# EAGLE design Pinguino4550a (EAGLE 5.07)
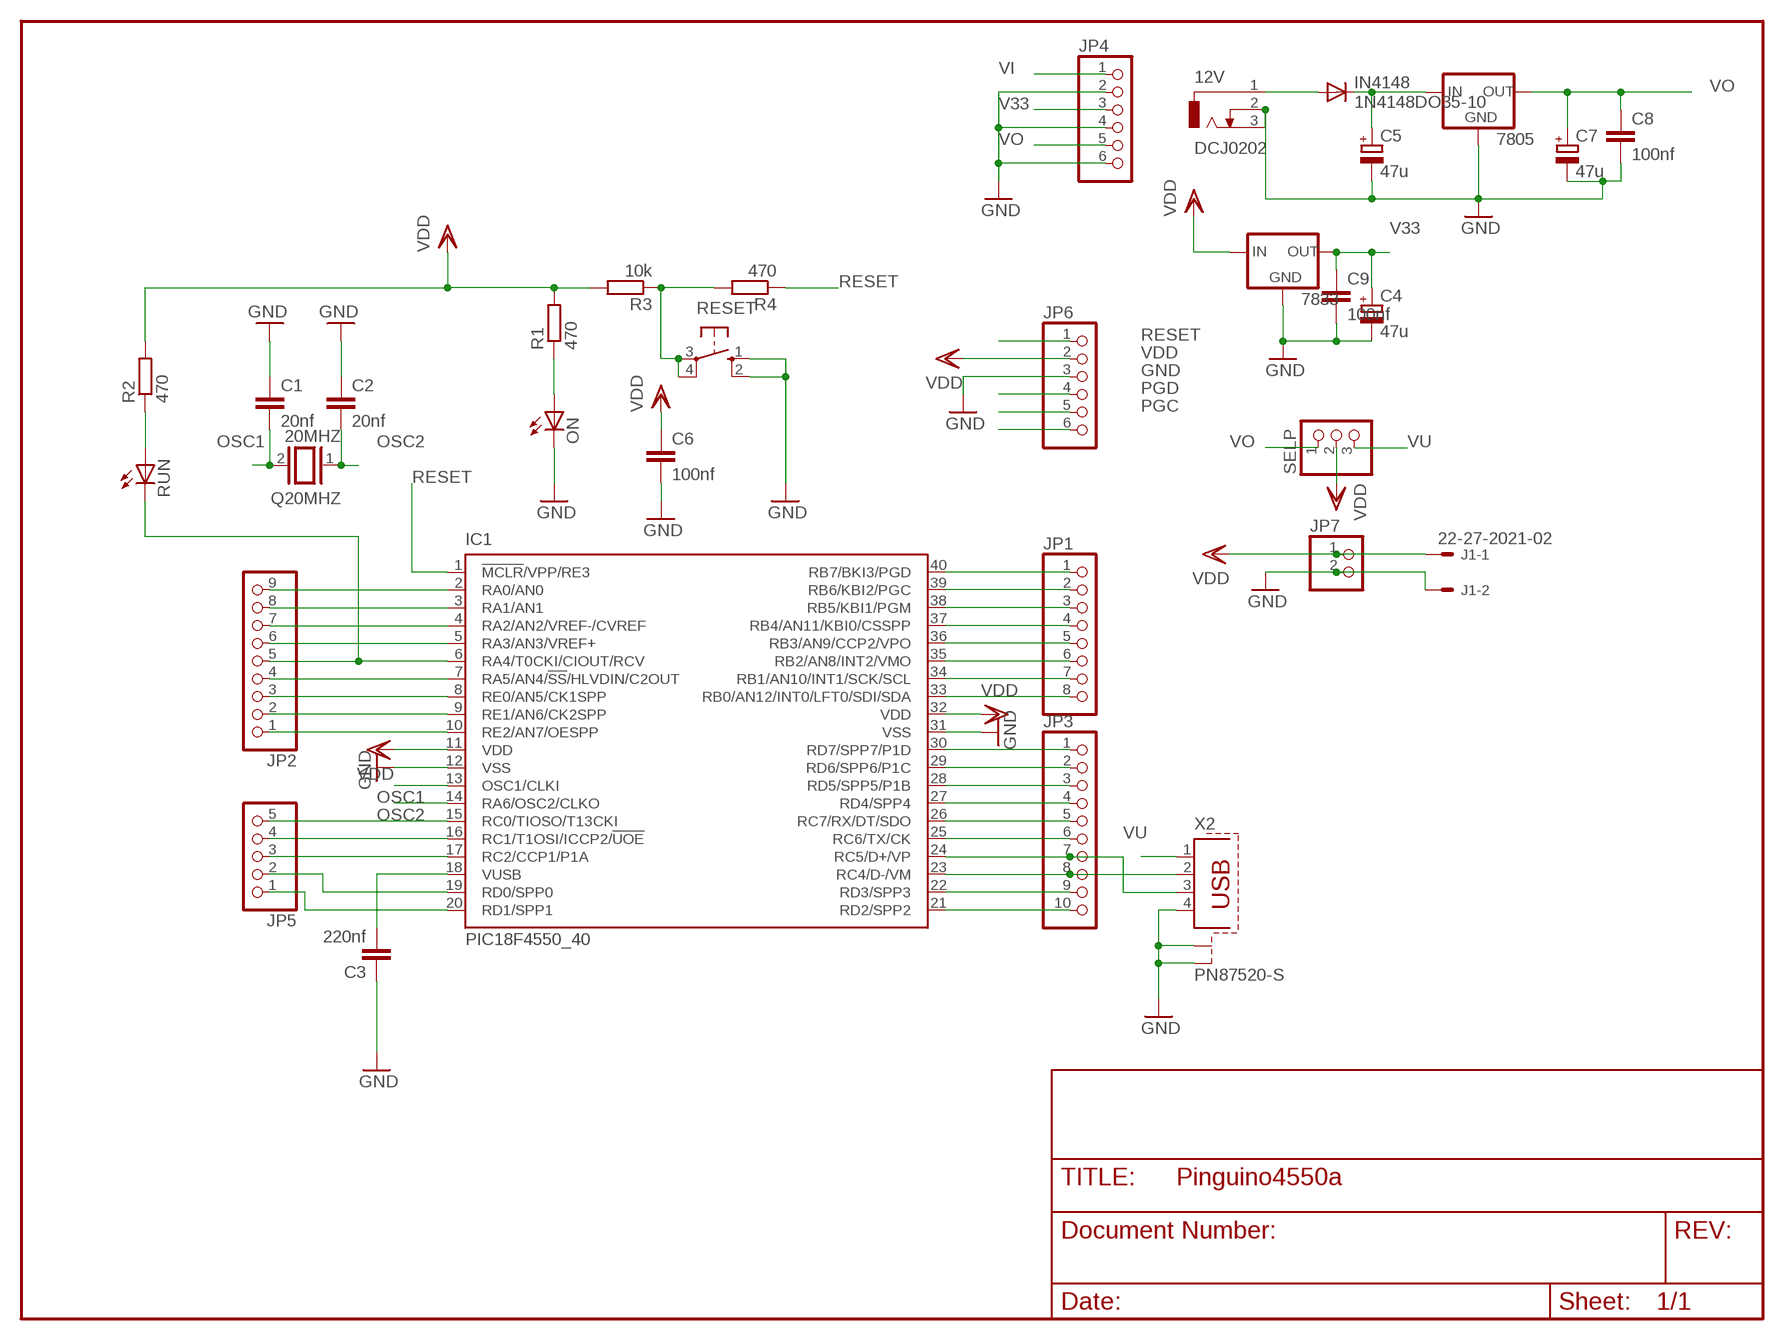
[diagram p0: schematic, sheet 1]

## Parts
12V  DCJ0202  [DCJ0202]
7805  78XXS  [78XXS]
7833  78XXS  [78XXS]
C1  20nf  C-EU025-024X044  [C025-024X044]
C2  20nf  C-EU025-024X044  [C025-024X044]
C3  220nf  C-EU025-024X044  [C025-024X044]
C4  47u  CPOL-EUE5-5  [E5-5]
C5  47u  CPOL-EUE5-5  [E5-5]
C6  100nf  C-EU025-024X044  [C025-024X044]
C7  47u  CPOL-EUE5-5  [E5-5]
C8  100nf  C-EU025-024X044  [C025-024X044]
C9  100nf  C-EU025-024X044  [C025-024X044]
IC1  PIC18F4550_40  [DIL40]
IN4148  1N4148DO35-10  [DO35-10]
J1  22-27-2021-02  [6410-02]
JP1  PINHD-1X8  [1X08]
JP2  PINHD-1X9  [1X09]
JP3  PINHD-1X10  [1X10]
JP4  PINHD-1X6  [1X06]
JP5  PINHD-1X5  [1X05]
JP6  PINHD-1X6  [1X06]
JP7  PINHD-1X2  [1X02]
ON  LED3MM  [LED3MM]
Q20MHZ  20MHZ  XTAL/S  [QS]
R1  470  R-EU_0204/7  [0204/7]
R2  470  R-EU_0204/7  [0204/7]
R3  10k  R-EU_0204/7  [0204/7]
R4  470  R-EU_0204/7  [0204/7]
RESET  10-XX  [B3F-10XX]
RUN  LED3MM  [LED3MM]
SELP  PINHD-1X3  [1X03]
X2  PN87520-S  [PN87520-S]

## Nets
GND: 12V.2 12V.3 7805.GND 7833.GND C1.1 C2.1 C3.1 C4.- C5.- C6.2 C7.- C8.2 C9.2 IC1.12(VSS) IC1.31(VSS) J1.2 JP4.2 JP4.4 JP4.6 JP6.3 JP7.2 ON.K(C) RESET.1(S) RESET.2(S1) X2.4 X2.S1 X2.S2
N$1: IC1.2(RA0/AN0) JP2.9
N$2: IC1.3(RA1/AN1) JP2.8
N$3: IC1.4(RA2/AN2/VREF-/CVREF) JP2.7
N$4: IC1.5(RA3/AN3/VREF+) JP2.6
N$5: R2.1 RUN.A
N$6: IC1.7(RA5/AN4/!SS!/HLVDIN/C2OUT) JP2.4
N$7: C3.2 IC1.18(VUSB)
N$8: IC1.8(RE0/AN5/CK1SPP) JP2.3
N$9: IC1.9(RE1/AN6/CK2SPP) JP2.2
N$10: IC1.30(RD7/SPP7/P1D) JP3.1
N$11: IC1.29(RD6/SPP6/P1C) JP3.2
N$12: IC1.33(RB0/AN12/INT0/LFT0/SDI/SDA) JP1.8
N$13: IC1.34(RB1/AN10/INT1/SCK/SCL) JP1.7
N$14: IC1.35(RB2/AN8/INT2/VMO) JP1.6
N$15: IC1.36(RB3/AN9/CCP2/VPO) JP1.5
N$16: IC1.37(RB4/AN11/KBI0/CSSPP) JP1.4
N$17: IC1.38(RB5/KBI1/PGM) JP1.3
N$18: R3.1 R4.2 RESET.3(P) RESET.4(P1)
N$19: IC1.10(RE2/AN7/OESPP) JP2.1
N$20: IC1.15(RC0/TIOSO/T13CKI) JP5.5
N$21: IC1.16(RC1/T1OSI/ICCP2/!UOE) JP5.4
N$22: IC1.17(RC2/CCP1/P1A) JP5.3
N$23: IC1.19(RD0/SPP0) JP5.2
N$24: 12V.1 IN4148.A
N$25: IC1.20(RD1/SPP1) JP5.1
N$26: JP6.6
N$27: IC1.28(RD5/SPP5/P1B) JP3.3
N$28: IC1.23(RC4/D-/VM) JP3.8 X2.2
N$29: IC1.24(RC5/D+/VP) JP3.7 X2.3
N$30: IC1.27(RD4/SPP4) JP3.4
N$31: IC1.26(RC7/RX/DT/SDO) JP3.5
N$32: IC1.25(RC6/TX/CK) JP3.6
N$33: IC1.22(RD3/SPP3) JP3.9
N$34: IC1.21(RD2/SPP2) JP3.10
N$41: IC1.6(RA4/T0CKI/CIOUT/RCV) JP2.5 RUN.K(C)
N$43: ON.A R1.1
OSC1: C1.2 IC1.13(OSC1/CLKI) Q20MHZ.2
OSC2: C2.2 IC1.14(RA6/OSC2/CLKO) Q20MHZ.1
PGC: IC1.39(RB6/KBI2/PGC) JP1.2 JP6.5
PGD: IC1.40(RB7/BKI3/PGD) JP1.1 JP6.4
RESET: IC1.1(!MCLR!/VPP/RE3) JP6.1 R4.1
V33: 7833.OUT C4.+ C9.1 JP4.3
VDD: 7833.IN C6.1 IC1.11(VDD) IC1.32(VDD) J1.1 JP6.2 JP7.1 R1.2 R2.2 R3.2 SELP.2
VI: 7805.IN C5.+ IN4148.C JP4.1
VO: 7805.OUT C7.+ C8.1 JP4.5 SELP.1
VU: SELP.3 X2.1

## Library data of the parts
12V = con-jack:DCJ0202: DC POWER JACK Source: DCJ0202.pdf
7805 7833 = v-reg:78XXS: VOLTAGE REGULATOR
C1-C3 C6 C8 C9 = rcl:C-EU: CAPACITOR, European symbol
C4 C5 C7 = rcl:CPOL-EU: POLARIZED CAPACITOR, European symbol
IC1 = microchip:PIC18F4*_40: USB Microcontrollers with nanoWatt Technology High-Performance, Enhanced Flash, 28/40/44-Pin, Source: http://ww1.microchip.com/downloads/en/devicedoc/39632c.pdf
IN4148 = diode:1N4148: DIODE
J1 = con-molex:22-?-02: CONNECTOR
JP1 = pinhead:PINHD-1X8: PIN HEADER
JP2 = pinhead:PINHD-1X9: PIN HEADER
JP3 = pinhead:PINHD-1X10: PIN HEADER
JP4 JP6 = pinhead:PINHD-1X6: PIN HEADER
JP5 = pinhead:PINHD-1X5: PIN HEADER
JP7 = pinhead:PINHD-1X2: PIN HEADER
ON RUN = led:LED: LED
Q20MHZ = special:XTAL/S: CRYSTAL
R1-R4 = rcl:R-EU_: RESISTOR, European symbol
RESET = switch-omron:10-XX: OMRON SWITCH
SELP = pinhead:PINHD-1X3: PIN HEADER
X2 = con-berg:PN87520-S

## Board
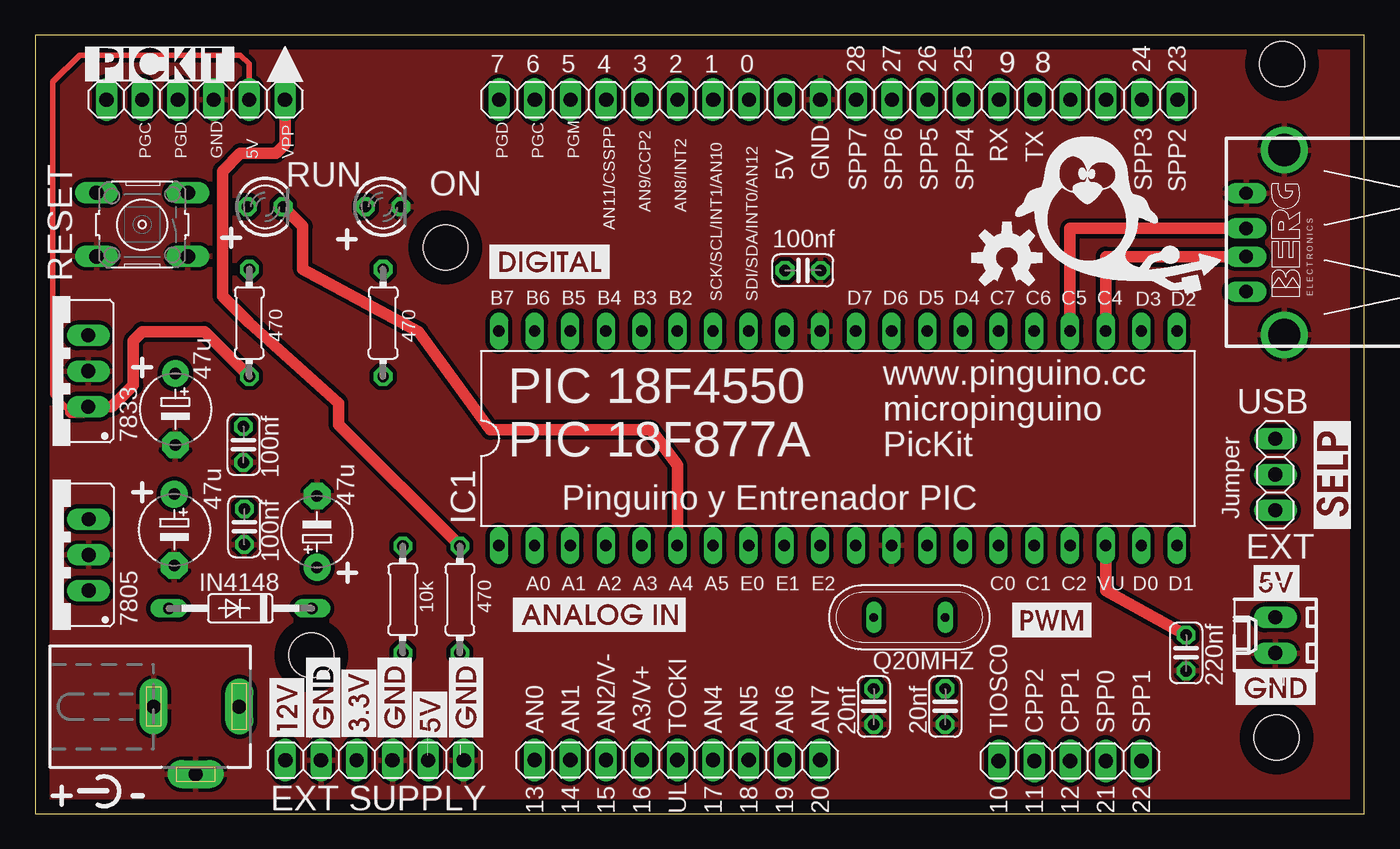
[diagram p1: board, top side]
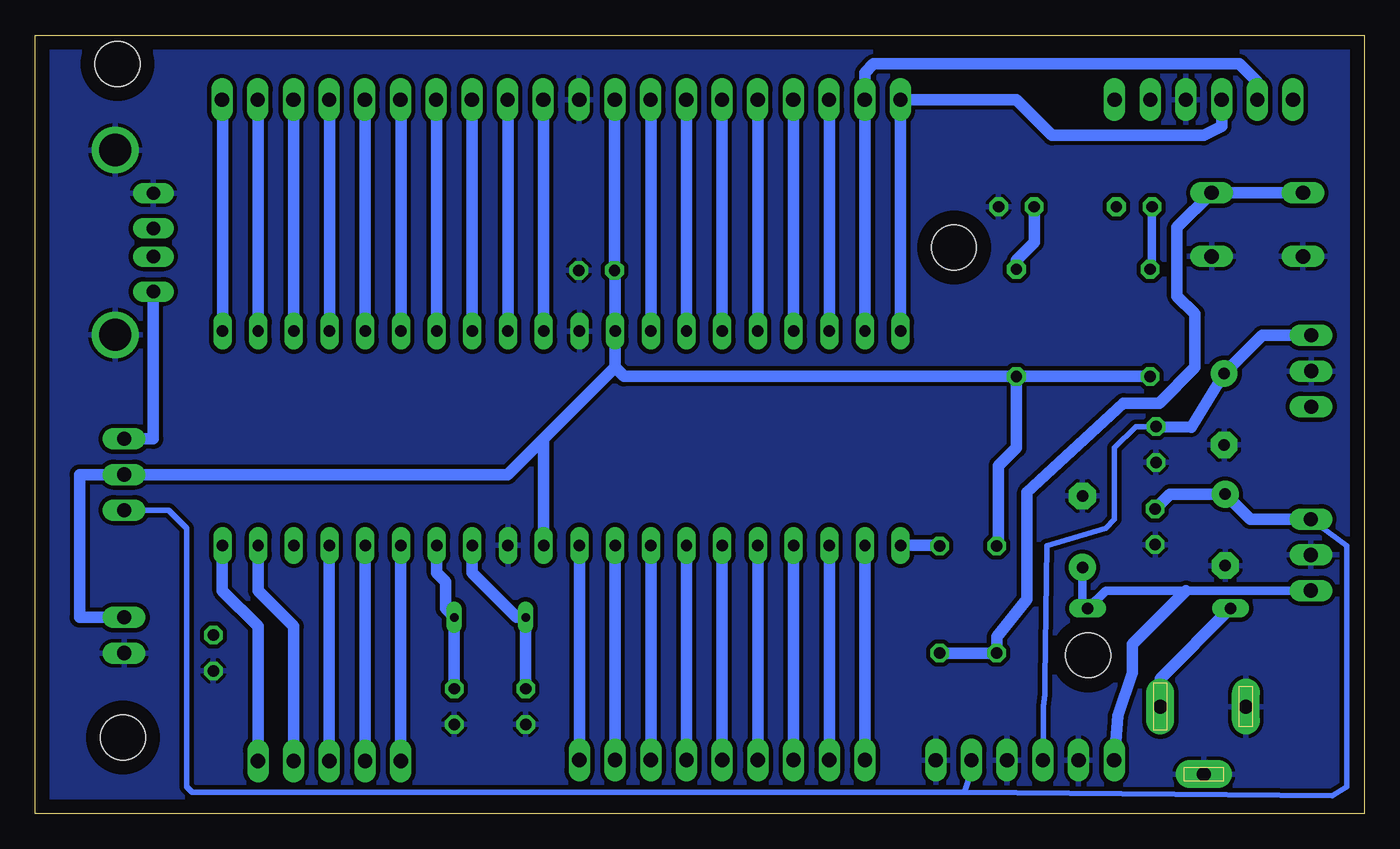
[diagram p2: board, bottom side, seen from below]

Size 94.6 x 55.39 mm. Coordinates in mm from the lower left corner, seen from the top.
Outline: 0,0 94.6,0 94.6,55.39 0,55.39 0,0
Copper layers (1*16): Top 0.035mm / dielectric 1.5mm / Bottom 0.035mm
Design rules "default": minimum track width 10mil, minimum drill 24mil, track to track 8mil, track to pad 8mil, pad to pad 8mil, via to via 8mil, smd to smd 8mil, copper to edge 40mil, drill to drill 8mil, minimum pad ring 10mil, minimum via ring 8mil, stop-mask expansion 4mil, vias tented up to drill 0mil, thermal gap 10mil
Holes 3.2 mm at 29.21,40.29 88.36,5.42 88.73,53.34 19.66,11.27

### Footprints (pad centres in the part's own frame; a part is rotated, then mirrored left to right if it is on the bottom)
DCJ0202 = drill 1 pad 2 long: 1 0,3.1; 2 4.8,0; 3 0,-3
78XXS = drill 1.016 long: GND 0,-2.54; IN -2.54,-2.54; OUT 2.54,-2.54
C025-024X044 = drill 0.813 octagon: 1 -1.27,0; 2 1.27,0
E5-5 = drill 0.813 pad 1.905 round: + -2.54,0 | drill 0.813 pad 1.905 octagon: - 2.54,0
DIL40 = drill 0.813 long: 1 -24.13,-7.62; 2 -21.59,-7.62; 3 -19.05,-7.62; 4 -16.51,-7.62; 5 -13.97,-7.62; 6 -11.43,-7.62; 7 -8.89,-7.62; 8 -6.35,-7.62; 9 -3.81,-7.62; 10 -1.27,-7.62; 11 1.27,-7.62; 12 3.81,-7.62; 13 6.35,-7.62; 14 8.89,-7.62; 15 11.43,-7.62; 16 13.97,-7.62; 17 16.51,-7.62; 18 19.05,-7.62; 19 21.59,-7.62; 20 24.13,-7.62; 21 24.13,7.62; 22 21.59,7.62; 23 19.05,7.62; 24 16.51,7.62; 25 13.97,7.62; 26 11.43,7.62; 27 8.89,7.62; 28 6.35,7.62; 29 3.81,7.62; 30 1.27,7.62; 31 -1.27,7.62; 32 -3.81,7.62; 33 -6.35,7.62; 34 -8.89,7.62; 35 -11.43,7.62; 36 -13.97,7.62; 37 -16.51,7.62; 38 -19.05,7.62; 39 -21.59,7.62; 40 -24.13,7.62
DO35-10 = drill 0.813 long: A 5.08,0; C -5.08,0
6410-02 = drill 1.016 long: 1 1.27,0; 2 -1.27,0
1X08 = drill 1.016 long: 1 -8.89,0; 2 -6.35,0; 3 -3.81,0; 4 -1.27,0; 5 1.27,0; 6 3.81,0; 7 6.35,0; 8 8.89,0
1X09 = drill 1.016 long: 1 -10.16,0; 2 -7.62,0; 3 -5.08,0; 4 -2.54,0; 5 0,0; 6 2.54,0; 7 5.08,0; 8 7.62,0; 9 10.16,0
1X10 = drill 1.016 long: 1 -11.43,0; 2 -8.89,0; 3 -6.35,0; 4 -3.81,0; 5 -1.27,0; 6 1.27,0; 7 3.81,0; 8 6.35,0; 9 8.89,0; 10 11.43,0
1X06 = drill 1.016 long: 1 -6.35,0; 2 -3.81,0; 3 -1.27,0; 4 1.27,0; 5 3.81,0; 6 6.35,0
1X05 = drill 1.016 long: 1 -5.08,0; 2 -2.54,0; 3 0,0; 4 2.54,0; 5 5.08,0
1X02 = drill 1.016 long: 1 -1.27,0; 2 1.27,0
LED3MM = drill 0.813 octagon: A -1.27,0; K 1.27,0
QS = drill 0.61 long: 1 -2.54,0; 2 2.54,0
0204/7 = drill 0.813 octagon: 1 -3.81,0; 2 3.81,0
B3F-10XX = drill 1.016 long: 1 -3.251,2.261; 2 3.251,2.261; 3 -3.251,-2.261; 4 3.251,-2.261
1X03 = drill 1.016 long: 1 -2.54,0; 2 0,0; 3 2.54,0
PN87520-S = drill 0.95 long: 1 -3.5,2.71; 2 -1,2.71; 3 1,2.71; 4 3.5,2.71 | drill 2.3 pad 2.9 round: S1 -6.57,0; S2 6.57,0

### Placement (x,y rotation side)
12V  11.43,7.62 270 top
7805  1.27,18.41 90 top
7833  1.24,31.5 90 top
C1  59.69,7.62 90 top
C2  64.77,7.62 90 top
C3  81.92,11.43 90 top
C4  9.98,28.78 270 top
C5  20.07,20.07 90 top
C6  54.64,38.66 0 top
C7  9.91,20.19 270 top
C8  14.88,20.42 270 top
C9  14.83,26.26 270 top
IC1  57.14,26.71 0 top
IN4148  14.61,14.61 180 top
J1  88.27,12.7 90 top
JP1  41.91,50.8 0 top
JP2  45.71,3.82 180 top
JP3  69.87,50.8 0 top
JP4  24.16,3.81 0 top
JP5  73.66,3.76 180 top
JP6  11.43,50.8 180 top
JP7  54.61,50.8 0 top
ON  24.77,43.18 0 top
Q20MHZ  62.23,13.97 180 top
R1  24.77,34.92 270 top
R2  15.24,34.92 270 top
R3  26.16,15.24 90 top
R4  30.23,15.24 270 top
RESET  7.62,41.91 180 top
RUN  16.38,43.18 0 top
SELP  88.27,24.13 90 top
X2  88.9,40.64 90 top

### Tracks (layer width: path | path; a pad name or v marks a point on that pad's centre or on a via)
GND
  pour Bottom (isolate 0.305): 0,55.4 94.3,55.4 94.3,0 0,0
  pour Top (isolate 0.305): 0,0 0,55.4 94.3,55.4 94.3,0
N$1
  Bottom 0.813: IC1.2 JP2.9
N$2
  Bottom 0.813: IC1.3 JP2.8
N$3
  Bottom 0.813: IC1.4 JP2.7
N$4
  Bottom 0.813: IC1.5 JP2.6
N$5
  Bottom 0.61: RUN.A 15.11,38.86 R2.1
N$6
  Bottom 0.813: IC1.7 JP2.4
N$7
  Top 0.813: IC1.18 76.2,15.88 C3.2
N$8
  Bottom 0.813: IC1.8 JP2.3
N$9
  Bottom 0.813: IC1.9 JP2.2
N$10
  Bottom 0.813: JP3.1 58.41,50.8 IC1.30
N$11
  Bottom 0.813: JP3.2 60.95,50.8 IC1.29
N$12
  Bottom 0.813: JP1.8 50.78,50.8 IC1.33
N$13
  Bottom 0.813: JP1.7 48.24,50.8 IC1.34
N$14
  Bottom 0.813: JP1.6 45.7,50.8 IC1.35
N$15
  Bottom 0.813: JP1.5 43.16,50.8 IC1.36
N$16
  Bottom 0.813: JP1.4 40.62,50.8 IC1.37
N$17
  Bottom 0.813: JP1.3 38.09,50.8 IC1.38
N$18
  Bottom 0.813: R4.2 R3.1 26.16,12.57 24,15.24 24,22.86 17.14,29.21 14.61,29.21 12.06,31.75 12.06,35.56 13.34,36.83 13.34,41.71 RESET.3 RESET.4
N$19
  Bottom 0.813: IC1.10 JP2.1
N$20
  Bottom 0.813: IC1.15 JP5.5
N$21
  Bottom 0.813: IC1.16 JP5.4
N$22
  Bottom 0.813: IC1.17 JP5.3
N$23
  Bottom 0.813: IC1.19 78.74,15.88 76.2,13.34 JP5.2
N$24
  Bottom 0.813: 12V.1 14.53,9.6 IN4148.A
N$25
  Bottom 0.813: IC1.20 81.28,15.88 78.74,13.34 JP5.1
N$27
  Bottom 0.813: JP3.3 63.48,50.8 IC1.28
N$28
  Top 0.813: X2.2 76.19,39.64 IC1.23
  Bottom 0.813: JP3.8 76.19,50.8 IC1.23
N$29
  Top 0.813: X2.3 73.64,41.64 IC1.24
  Bottom 0.813: JP3.7 73.64,50.8 IC1.24
N$30
  Bottom 0.813: JP3.4 66.03,50.8 IC1.27
N$31
  Bottom 0.813: JP3.5 68.56,50.8 IC1.26
N$32
  Bottom 0.813: JP3.6 71.11,50.8 IC1.25
N$33
  Bottom 0.813: JP3.9 78.72,50.8 IC1.22
N$34
  Bottom 0.813: JP3.10 81.27,50.8 IC1.21
N$41
  Top 0.813: IC1.6 45.7,24.78 43.81,27.3 32.38,27.3 27.3,34.29 19.05,38.73 19.05,41.78 RUN.K
  Bottom 0.813: IC1.6 JP2.5
N$43
  Bottom 0.813: R1.1 24.77,39.37 23.5,40.64 ON.A
OSC1
  Bottom 0.813: IC1.13 63.48,17.13 60.33,13.97 Q20MHZ.2 C1.2
OSC2
  Bottom 0.813: IC1.14 66.03,17.13 65.41,16.51 65.41,14.61 Q20MHZ.1 C2.2
PGC
  Bottom 0.813: IC1.39 35.55,50.8 JP1.2 35.56,52.7 34.92,53.34 8.89,53.34 7.62,52.07 JP6.5
PGD
  Bottom 0.813: IC1.40 JP1.1 24.77,50.8 22.23,48.26 11.43,48.26 10.16,48.9 JP6.4
RESET
  Top 0.813: JP6.1 17.78,47.62 17.14,46.99 14.61,46.99 13.34,45.72 13.34,36.83 15.24,34.92 21.59,29.21 21.59,27.69 R4.1
  Bottom 0.813: IC1.1 30.27,19.09 R4.1
V33
  Bottom 0.406: C9.1 16.28,27.53 17.78,26.04 17.78,20.95 18.41,20.32 22.61,19.05 22.73,9.53 22.73,8.51 22.86,7.62 22.86,4.55 JP4.3
  Bottom 0.813: 7833.OUT 7.26,34.04 C4.+ 12.32,27.51 C9.1
VDD
  Top 0.406: JP6.2 15.24,53.34 14.61,53.98 3.17,53.98 1.27,52.07 1.27,29.84 2.54,28.57
  Top 0.813: 2.54,28.57 3.4,28.57 7833.IN 5.46,28.96 6.99,30.48 6.99,33.66 7.62,34.29 12.06,34.29 R2.2
  Bottom 0.813: JP7.1 53.37,50.8 C6.1 53.33,38.66 IC1.32 53.34,34.31 53.34,31.75 | J1.1 91.44,13.97 91.44,24.13 SELP.2 60.96,24.13 58.41,26.68 | R1.2 52.7,31.11 53.34,31.75 | 58.41,26.68 IC1.11 | 53.34,31.75 58.41,26.68 | R2.2 R1.2 | R1.2 24.77,26.04 26.04,24.77 26.04,19.18 R3.2
VI
  Bottom 0.61: 7805.IN 12.7,15.88 18.41,15.88 IN4148.C 20.07,14.99 C5.+
  Bottom 0.813: JP4.1 17.55,6.96 16.51,10.03 16.51,12.06 12.7,15.88
VO
  Bottom 0.406: 28.45,1.52 27.96,3.07 JP4.5 | 28.45,1.52 83.44,1.52 83.82,1.91 83.82,20.32 85.09,21.59 SELP.1 | 28.45,1.52 2.29,1.27 1.27,1.91 1.27,19.05 7805.OUT
  Bottom 0.813: 7805.OUT 8.13,20.95 C7.+ 13.84,22.73 C8.1
VU
  Bottom 0.813: SELP.3 86.19,26.67 X2.1

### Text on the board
tNames: 7 | 6 | 5 | 4 | 3 | 2 | 1 | 0 | 28 | 27 | 26 | 25 | 9 | 8 | 24 | 23 | PGC | PGD | GND | 5V | VPP | PGD | PGC | PGM | RX | TX | 5V | GND | SPP7 | SPP6 | SPP5 | SPP4 | SPP3 | SPP2 | AN9/CCP2 | AN8/INT2 | AN11/CSSPP | B7 | B6 | B5 | B4 | B3 | B2 | SCK/SCL/INT1/AN10 | SDI/SDA/INT0/AN12 | D7 | D6 | D5 | D4 | C7 | C6 | C5 | C4 | D3 | D2 | www.pinguino.cc | USB | PIC 18F4550 | micropinguino | PIC 18F877A | PicKit | Pinguino y Entrenador PIC | Jumper | EXT | A0 | A1 | A2 | A3 | A4 | A5 | E0 | E1 | E2 | C0 | C1 | C2 | VU | D0 | D1 | AN0 | AN1 | AN2/V- | A3/V+ | TOCKI | AN4 | AN5 | AN6 | AN7 | TIOSC0 | CPP2 | CPP1 | SPP0 | SPP1 | /home/julio/eagle/pinguino/12v.bmp | EXT SUPPLY | 13 | 14 | 15 | 16 | UL | 17 | 18 | 19 | 20 | 10 | 11 | 12 | 21 | 22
